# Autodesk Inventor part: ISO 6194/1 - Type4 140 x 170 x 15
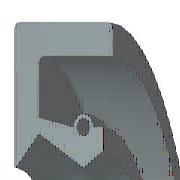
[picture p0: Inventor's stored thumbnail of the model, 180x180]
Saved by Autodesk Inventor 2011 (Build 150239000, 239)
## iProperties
Created: 2010-02
Part Number: ISO 6194/1 - Type4 140 x 170 x 15
Material: Rubber
Description: Rotary shaft lip type seals
Document SubType Name: Modeling
Standard: ISO 6194/1
Designer: 129877
Standard Revision: First edition 1984-11-15
Standards Organization: ISO
Language: en-US
Size Designation: Type4 140 x 170 x 15
Categories: <MemberInstance><Categories><Category DisplayName="Shaft Parts" InternalName="7f7aeb1f-a693-4053-b835-cee3144e0d98" Mnemonic="SHFT"><Category DisplayName="Seali
Density: 0.93 g/cm^3
Mass: 57.984 g
Surface Area: 392.668 cm^2
Volume: 62.3484 cm^3
IsCustomPart: 0
Author: 129877
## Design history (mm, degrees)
revolve "Body" stored, may be unused: angle "d17" = 90 deg
revolve "Spring1" stored, may be unused: angle "d18" = 90 deg
body "Solid1"
sketch "Sketch1"
  geometry: L1 (0, 85)-(15, 85); L2 (15, 81.25)-(3.75, 81.25); L3 (3.75, 73.75)-(10.5, 70); L4 (10.5, 70)-(0, 70); L5 (0, 0)-(9.586, 0) reference; L6 (10.5, 70)-(13.5, 71.875); L7 (0, 18)-(0, -3) reference; L8 (-1.941, 0)-(11.507, 0) reference; L9 (9, 74.5)-(3.75, 75.55); L10 (3.75, 75.55)-(3.75, 81.25); L11 (0, 85)-(0, 70.188); L12 (10.5, 70)-(0, 70); L13 (3.75, 73.75)-(0.325, 70.06); L14 (15, 85)-(15, 81.25); L15 (12, 74.5)-(13.5, 74.5); L16 (13.5, 74.5)-(13.5, 71.875); C1 r 0.975 at (10.5, 74.5); A1 r 1.5 centre (10.5, 74.5) between (12, 74.5) and (9, 74.5); A2 r 0.188 centre (0.187, 70.188) between (0, 70.188) and (0.325, 70.06); 1 further point
  constraints: 28 end point, 5 horizontal alignment, 5 point on line, 4 point on circle, 4 vertical alignment, 3 centre point, 3 tangent, 2 collinear, 2 horizontal, 2 perpendicular, 1 coincident, 1 parallel
  dimensions: "d0" = 170 diameter of L1 L5 (= SD2); "d1" = 3.75 distance of L1.end L2.start (= SD); "d2" = 1.95 diameter of C1 (= SPDI); "d3" = 3 diameter of A1 (= SPDA); "d4" = 140 diameter of L3.end L5 (= NND); "d5" = 147.5 diameter of L3.start L5 (= TKDM); "d7" = 151.1 diameter of L9.end L5 (= TKDM + 0.24 x SWDT); "d8" = 3.75 distance between parallel lines of L11 L10 (= SD); "d9" = 10.5 distance from line of L11 C1.centre (= SPDST); "d10" = 149 diameter of C1.centre L5 (= HLDM); "d11" = 0.1875 radius of A2 (= 0.25 x LAB); "d12" = 13.5 distance between parallel lines of L11 L16 (= SDI); "d13" = 143.75 diameter of L6.end L5 (= ABDM); "d14" = 15 distance from line of L11 L1.end (= SWDT)
fillet "Fillet1" dims "d6" = 1 (= RR)
other parameters: "SD2" = 170 [user parameter; used in 1 equation term], "SWDT" = 15 [user parameter; used in 2 equation terms], "RR" = 1 [user parameter; used in 1 equation term], "SD" = 3.75 [user parameter; used in 2 equation terms], "NND" = 140 [user parameter; used in 1 equation term], "SPDA" = 3 [user parameter; used in 1 equation term], "SPDI" = 1.95 [user parameter; used in 1 equation term], "TKDM" = 147.5 [user parameter; used in 2 equation terms], "HLDM" = 149 [user parameter; used in 1 equation term], "ABDM" = 143.75 [user parameter; used in 1 equation term], "SDI" = 13.5 [user parameter; used in 1 equation term], "SPDST" = 10.5 [user parameter; used in 1 equation term], "LAB" = 0.75 [user parameter; used in 1 equation term], "d15" = 0, "d16" = 0, "d19" = 0
